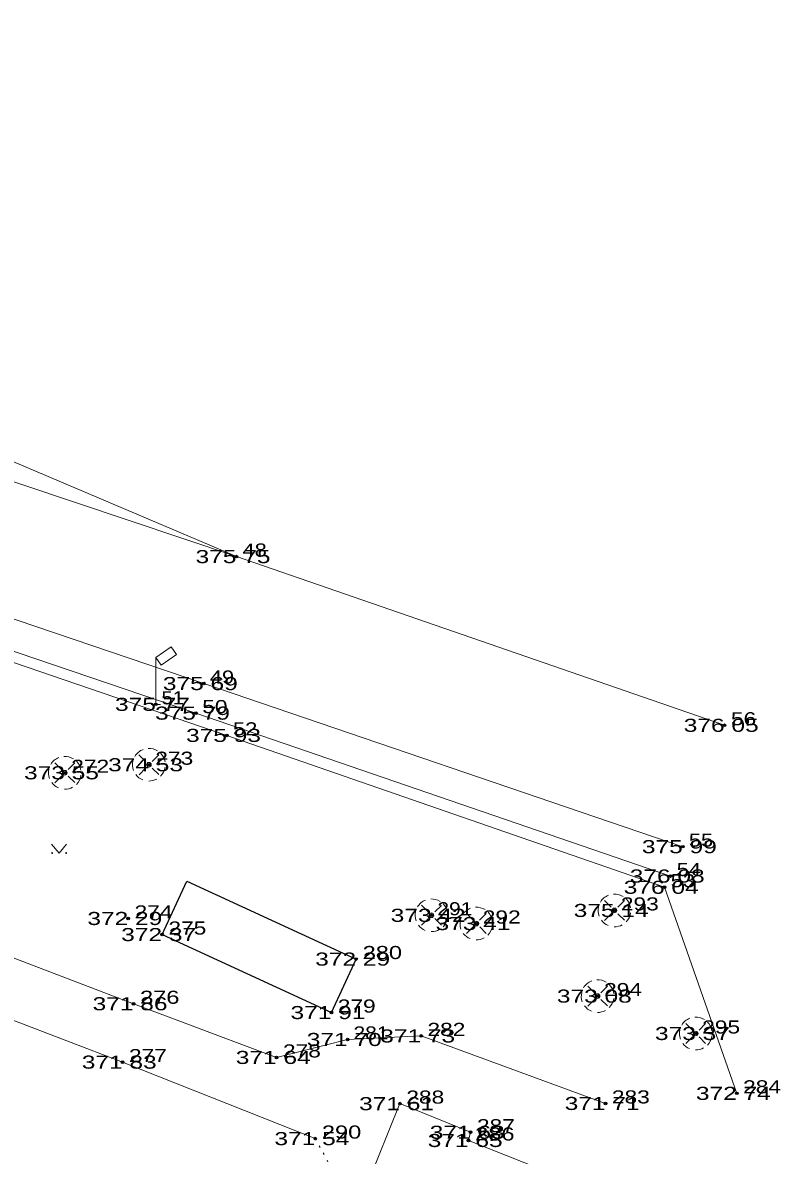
# Model space of a CAD drawing. Extents: x -789669 to -789458, y -977587 to -977420.
# Drawn here: x -789498.6 to -789458.1, y -977511.4 to -977450.8 of the extents above; entities that cross this region are included whole.
import ezdxf
from ezdxf.enums import TextEntityAlignment as Align

# ---------------------------------------------------------------- set-up
doc = ezdxf.new("R2010")
doc.units = 0
doc.header["$LTSCALE"] = 0.28
doc.header["$PDMODE"] = 32
doc.header["$PDSIZE"] = 0.14
doc.linetypes.add('DOTTED', pattern=[1.5, 0.3, -1.2])
for name, color, linetype, lineweight in [('1', 7, 'Continuous', 13), ('2', 7, 'Continuous', 13), ('3', 7, 'Continuous', 13), ('33', 7, 'Continuous', 13), ('4', 7, 'Continuous', 13), ('9', 7, 'Continuous', 25)]:
    doc.layers.add(name, color=color, linetype=linetype, lineweight=lineweight)
for name, color, linetype in [('57', 7, 'Continuous'), ('58', 7, 'Continuous'), ('59', 7, 'Continuous')]:
    doc.layers.add(name, color=color, linetype=linetype)

msp = doc.modelspace()

# ---------------------------------------------------------------- linework, layer by layer
at = {"layer": '1'}
for p, q in [((-789488.92, -977486.15), (-789509.64, -977479.12)), ((-789461.05, -977488.38), (-789487.17, -977479.36)), ((-789463.29, -977494.87), (-789488.92, -977486.15))]:
    msp.add_line(p, q, dxfattribs=at)
at = {"layer": '1', "linetype": 'DOTTED'}
msp.add_line((-789482.95, -977510.48), (-789480.79, -977514.44), dxfattribs=at)
at = {"layer": '1'}
for points in [[(-789652.33, -977422.61), (-789627.98, -977430.97), (-789609.02, -977437.54), (-789583.63, -977446.35), (-789563.97, -977453.25), (-789542.04, -977460.63), (-789524.21, -977466.84), (-789507.23, -977472.64), (-789487.17, -977479.36)], [(-789604.26, -977448.38), (-789586.79, -977454.41), (-789566.59, -977461.37), (-789545.35, -977468.71), (-789526.33, -977475.15), (-789510.21, -977480.66), (-789489.34, -977487.73), (-789463.94, -977496.44)], [(-789467.42, -977508.6), (-789477.29, -977504.99), (-789481.22, -977505.18), (-789485.02, -977506.14), (-789492.68, -977503.27), (-789501.04, -977500.09), (-789503.9, -977498.24), (-789506.28, -977496), (-789508.64, -977493.39), (-789510.52, -977490.57), (-789512.27, -977487.46), (-789516.29, -977480.46), (-789515.91, -977479.22)], [(-789482.95, -977510.48), (-789493.26, -977506.39), (-789502.22, -977502.97), (-789513.09, -977498.78), (-789524.32, -977494.44)], [(-789480.79, -977514.44), (-789478.42, -977508.61), (-789474.64, -977510.14), (-789474.64, -977510.14), (-789474.75, -977510.58), (-789468.72, -977512.97)]]:
    msp.add_lwpolyline(points, dxfattribs=at)
at = {"layer": '2'}
msp.add_lwpolyline([(-789651.99, -977420.32), (-789627.42, -977429.7), (-789608.58, -977435.72), (-789582.71, -977444.73), (-789563.37, -977451.38), (-789541.29, -977458.45), (-789523.64, -977464.38), (-789506.63, -977471.11), (-789487.17, -977479.36)], dxfattribs=at)
at = {"layer": '3'}
msp.add_lwpolyline([(-789515.91, -977479.22), (-789510.42, -977481.15), (-789487.68, -977488.92), (-789464.26, -977497.04), (-789460.4, -977508.06)], dxfattribs=at)
at = {"layer": '33'}
for p, q in [((-789491.48, -977484.76), (-789491.48, -977487.26)), ((-789491.73, -977487.26), (-789491.23, -977487.26))]:
    msp.add_line(p, q, dxfattribs=at)
msp.add_lwpolyline([(-789491.48, -977484.76), (-789490.66, -977484.187), (-789490.374, -977484.597), (-789491.194, -977485.17)], close=True, dxfattribs=at)
at = {"layer": '4'}
for p, q in [((-789492.384, -977489.952), (-789492.027, -977490.308)), ((-789491.324, -977489.96), (-789491.677, -977490.313)), ((-789496.884, -977490.382), (-789496.527, -977490.738)), ((-789495.824, -977490.39), (-789496.177, -977490.743)), ((-789492.38, -977491.023), (-789492.028, -977490.672)), ((-789491.85, -977490.496), (-789491.85, -977490.484)), ((-789491.676, -977490.667), (-789491.324, -977491.017)), ((-789496.88, -977491.453), (-789496.528, -977491.102)), ((-789496.35, -977490.926), (-789496.35, -977490.914)), ((-789496.176, -977491.097), (-789495.824, -977491.447)), ((-789477.264, -977498.002), (-789476.907, -977498.358)), ((-789476.204, -977498.01), (-789476.557, -977498.363)), ((-789467.474, -977497.742), (-789467.117, -977498.098)), ((-789466.414, -977497.75), (-789466.767, -977498.103)), ((-789476.73, -977498.546), (-789476.73, -977498.534)), ((-789474.864, -977498.442), (-789474.507, -977498.798)), ((-789473.804, -977498.45), (-789474.157, -977498.803)), ((-789467.47, -977498.813), (-789467.118, -977498.462)), ((-789466.94, -977498.286), (-789466.94, -977498.274)), ((-789466.766, -977498.457), (-789466.414, -977498.807)), ((-789477.26, -977499.073), (-789476.908, -977498.722)), ((-789476.556, -977498.717), (-789476.204, -977499.067)), ((-789474.86, -977499.513), (-789474.508, -977499.162)), ((-789474.33, -977498.986), (-789474.33, -977498.974)), ((-789474.156, -977499.157), (-789473.804, -977499.507)), ((-789468.374, -977502.322), (-789468.017, -977502.678)), ((-789467.84, -977502.866), (-789467.84, -977502.854)), ((-789467.314, -977502.33), (-789467.667, -977502.683)), ((-789468.37, -977503.393), (-789468.018, -977503.042)), ((-789467.666, -977503.037), (-789467.314, -977503.387)), ((-789463.124, -977504.322), (-789462.767, -977504.678)), ((-789462.064, -977504.33), (-789462.417, -977504.683)), ((-789463.12, -977505.393), (-789462.768, -977505.042)), ((-789462.59, -977504.866), (-789462.59, -977504.854)), ((-789462.416, -977505.037), (-789462.064, -977505.387))]:
    msp.add_line(p, q, dxfattribs=at)
for points in [[(-789497.058, -977494.732), (-789496.656, -977495.211), (-789496.254, -977494.732)], [(-789497.03, -977495.188), (-789497.016, -977495.196), (-789497.011, -977495.211), (-789497.017, -977495.224), (-789497.03, -977495.232), (-789497.046, -977495.224), (-789497.052, -977495.211), (-789497.048, -977495.197), (-789497.037, -977495.191), (-789497.022, -977495.197), (-789497.017, -977495.211), (-789497.02, -977495.221), (-789497.03, -977495.226), (-789497.041, -977495.221), (-789497.047, -977495.21), (-789497.042, -977495.2), (-789497.037, -977495.197), (-789497.026, -977495.201), (-789497.021, -977495.211), (-789497.027, -977495.218), (-789497.035, -977495.216), (-789497.04, -977495.208), (-789497.035, -977495.203), (-789497.027, -977495.207), (-789497.03, -977495.211)], [(-789496.28, -977495.189), (-789496.266, -977495.197), (-789496.261, -977495.212), (-789496.267, -977495.225), (-789496.28, -977495.233), (-789496.296, -977495.225), (-789496.302, -977495.212), (-789496.298, -977495.198), (-789496.287, -977495.192), (-789496.272, -977495.198), (-789496.267, -977495.212), (-789496.27, -977495.222), (-789496.28, -977495.227), (-789496.291, -977495.222), (-789496.297, -977495.211), (-789496.292, -977495.201), (-789496.287, -977495.198), (-789496.276, -977495.202), (-789496.271, -977495.212), (-789496.277, -977495.219), (-789496.285, -977495.217), (-789496.29, -977495.209), (-789496.285, -977495.204), (-789496.277, -977495.208), (-789496.28, -977495.212)]]:
    msp.add_lwpolyline(points, dxfattribs=at)
for centre, radius in [((-789496.3539, -977490.9194), 0.125), ((-789491.8539, -977490.4894), 0.125), ((-789497.031, -977495.211), 0.025), ((-789496.281, -977495.211), 0.025), ((-789476.7339, -977498.5394), 0.125), ((-789466.9439, -977498.2794), 0.125), ((-789474.3339, -977498.9794), 0.125), ((-789467.8439, -977502.8594), 0.125), ((-789462.5939, -977504.8594), 0.125)]:
    msp.add_circle(centre, radius, dxfattribs=at)
for centre, start, end in [((-789496.3539, -977490.9194), 111.04924, 149.34666), ((-789496.3539, -977490.9194), 57.94289, 92.85253), ((-789491.8539, -977490.4894), 111.04924, 149.34666), ((-789491.8539, -977490.4894), 57.94289, 92.85253), ((-789491.8539, -977490.4894), 9.68453, 44.47714), ((-789496.3539, -977490.9194), 166.76695, 200.11735), ((-789496.3539, -977490.9194), 9.68453, 44.47714), ((-789491.8539, -977490.4894), 166.76695, 200.11735), ((-789491.8539, -977490.4894), 315.09105, 351.67435), ((-789496.3539, -977490.9194), 315.09105, 351.67435), ((-789491.8539, -977490.4894), 217.06959, 247.69959), ((-789491.8539, -977490.4894), 269.18965, 298.56841), ((-789496.3539, -977490.9194), 217.06959, 247.69959), ((-789496.3539, -977490.9194), 269.18965, 298.56841), ((-789466.9439, -977498.2794), 111.04924, 149.34666), ((-789466.9439, -977498.2794), 57.94289, 92.85253), ((-789476.7339, -977498.5394), 111.04924, 149.34666), ((-789476.7339, -977498.5394), 57.94289, 92.85253), ((-789476.7339, -977498.5394), 9.68453, 44.47714), ((-789466.9439, -977498.2794), 9.68453, 44.47714), ((-789476.7339, -977498.5394), 166.76695, 200.11735), ((-789476.7339, -977498.5394), 315.09105, 351.67435), ((-789474.3339, -977498.9794), 111.04924, 149.34666), ((-789474.3339, -977498.9794), 57.94289, 92.85253), ((-789474.3339, -977498.9794), 9.68453, 44.47714), ((-789466.9439, -977498.2794), 166.76695, 200.11735), ((-789466.9439, -977498.2794), 315.09105, 351.67435), ((-789476.7339, -977498.5394), 217.06959, 247.69959), ((-789474.3339, -977498.9794), 166.76695, 200.11735), ((-789474.3339, -977498.9794), 315.09105, 351.67435), ((-789466.9439, -977498.2794), 217.06959, 247.69959), ((-789466.9439, -977498.2794), 269.18965, 298.56841), ((-789476.7339, -977498.5394), 269.18965, 298.56841), ((-789474.3339, -977498.9794), 217.06959, 247.69959), ((-789474.3339, -977498.9794), 269.18965, 298.56841), ((-789467.8439, -977502.8594), 111.04924, 149.34666), ((-789467.8439, -977502.8594), 57.94289, 92.85253), ((-789467.8439, -977502.8594), 9.68453, 44.47714), ((-789467.8439, -977502.8594), 166.76695, 200.11735), ((-789467.8439, -977502.8594), 217.06959, 247.69959), ((-789467.8439, -977502.8594), 315.09105, 351.67435), ((-789467.8439, -977502.8594), 269.18965, 298.56841), ((-789462.5939, -977504.8594), 111.04924, 149.34666), ((-789462.5939, -977504.8594), 57.94289, 92.85253), ((-789462.5939, -977504.8594), 166.76695, 200.11735), ((-789462.5939, -977504.8594), 9.68453, 44.47714), ((-789462.5939, -977504.8594), 315.09105, 351.67435), ((-789462.5939, -977504.8594), 217.06959, 247.69959), ((-789462.5939, -977504.8594), 269.18965, 298.56841)]:
    msp.add_arc(centre, 0.875, start, end, dxfattribs=at)
at = {"layer": '57'}
for p in [(-789487.17, -977479.36), (-789488.92, -977486.15), (-789491.48, -977487.26), (-789489.34, -977487.73), (-789461.05, -977488.38), (-789487.68, -977488.92), (-789491.85, -977490.49), (-789496.35, -977490.92), (-789463.29, -977494.87), (-789463.94, -977496.44), (-789464.26, -977497.04), (-789492.96, -977498.71), (-789476.73, -977498.54), (-789466.94, -977498.28), (-789474.33, -977498.98), (-789491.15, -977499.57), (-789480.77, -977500.88), (-789467.84, -977502.86), (-789492.68, -977503.27), (-789482.09, -977503.74), (-789481.22, -977505.18), (-789477.29, -977504.99), (-789462.59, -977504.86), (-789493.26, -977506.39), (-789485.02, -977506.14), (-789460.4, -977508.06), (-789478.42, -977508.61), (-789467.42, -977508.6), (-789474.64, -977510.14), (-789482.95, -977510.48), (-789474.75, -977510.58)]:
    msp.add_point(p, dxfattribs=at)
at = {"layer": '9'}
for points in [[(-789491.15, -977499.57), (-789489.83, -977496.71), (-789480.77, -977500.88)], [(-789491.15, -977499.57), (-789482.09, -977503.74), (-789480.77, -977500.88)]]:
    msp.add_lwpolyline(points, dxfattribs=at)

# ---------------------------------------------------------------- texts
at = {"layer": '58'}
for s, width, p in [(' 48', 1.25, (-789487.17, -977479.36)), (' 49', 1.25, (-789488.92, -977486.15)), (' 51', 1.15, (-789491.48, -977487.26)), (' 50', 1.3, (-789489.34, -977487.73)), (' 56', 1.3, (-789461.05, -977488.38)), (' 52', 1.25, (-789487.68, -977488.92)), (' 273', 1.3, (-789491.85, -977490.49)), (' 272', 1.3, (-789496.35, -977490.92)), (' 55', 1.25, (-789463.29, -977494.87)), (' 54', 1.25, (-789463.94, -977496.44)), (' 53', 1.25, (-789464.26, -977497.04)), (' 274', 1.3, (-789492.96, -977498.71)), (' 291', 1.2, (-789476.73, -977498.54)), (' 293', 1.3, (-789466.94, -977498.28)), (' 292', 1.3, (-789474.33, -977498.98)), (' 275', 1.3, (-789491.15, -977499.57)), (' 280', 1.35, (-789480.77, -977500.88)), (' 294', 1.3, (-789467.84, -977502.86)), (' 276', 1.35, (-789492.68, -977503.27)), (' 279', 1.3, (-789482.09, -977503.74)), (' 281', 1.2, (-789481.22, -977505.18)), (' 282', 1.3, (-789477.29, -977504.99)), (' 295', 1.3, (-789462.59, -977504.86)), (' 277', 1.3, (-789493.26, -977506.39)), (' 278', 1.3, (-789485.02, -977506.14)), (' 284', 1.3, (-789460.4, -977508.06)), (' 288', 1.3, (-789478.42, -977508.61)), (' 283', 1.3, (-789467.42, -977508.6)), (' 287', 1.3, (-789474.64, -977510.14)), (' 290', 1.35, (-789482.95, -977510.48)), (' 286', 1.35, (-789474.75, -977510.58))]:
    msp.add_text(s, height=0.7, dxfattribs=dict(at, width=width)).set_placement(p)
at = {"layer": '59', "width": 1.4}
for s, p in [('375 75 ', (-789487.17, -977479.71)), ('375 69 ', (-789488.92, -977486.5)), ('375 77 ', (-789491.48, -977487.61)), ('375 79 ', (-789489.34, -977488.08)), ('376 05 ', (-789461.05, -977488.73)), ('375 93 ', (-789487.68, -977489.27)), ('374 53 ', (-789491.85, -977490.84)), ('373 55 ', (-789496.35, -977491.27)), ('375 99 ', (-789463.29, -977495.22)), ('376 08 ', (-789463.94, -977496.79)), ('376 04 ', (-789464.26, -977497.39)), ('375 14 ', (-789466.94, -977498.63)), ('372 29 ', (-789492.96, -977499.06)), ('373 42 ', (-789476.73, -977498.89)), ('373 41 ', (-789474.33, -977499.33)), ('372 37 ', (-789491.15, -977499.92)), ('372 29 ', (-789480.77, -977501.23)), ('371 86 ', (-789492.68, -977503.62)), ('373 08 ', (-789467.84, -977503.21)), ('371 91 ', (-789482.09, -977504.09)), ('371 73 ', (-789477.29, -977505.34)), ('373 37 ', (-789462.59, -977505.21)), ('371 70 ', (-789481.22, -977505.53)), ('371 64 ', (-789485.02, -977506.49)), ('371 83 ', (-789493.26, -977506.74)), ('372 74 ', (-789460.4, -977508.41)), ('371 61 ', (-789478.42, -977508.96)), ('371 71 ', (-789467.42, -977508.95)), ('371 54 ', (-789482.95, -977510.83)), ('371 63 ', (-789474.64, -977510.49)), ('371 65 ', (-789474.75, -977510.93))]:
    msp.add_text(s, height=0.7, dxfattribs=at).set_placement(p, align=Align.CENTER)

doc.saveas('drawing.dxf')
